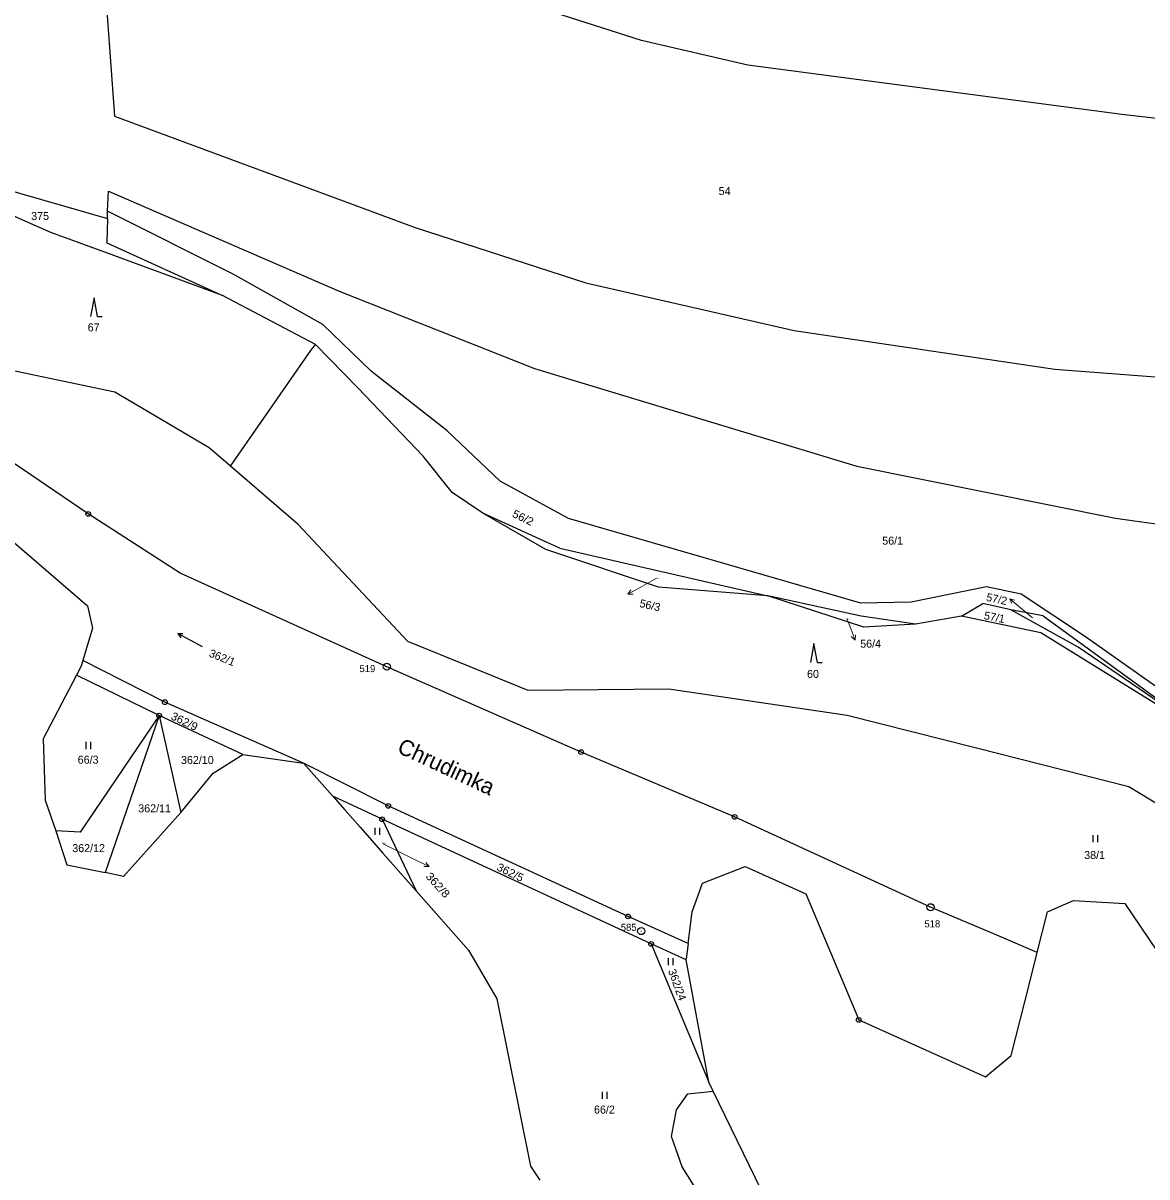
# Model space of a CAD drawing. Extents: x -645290 to -643454, y -1064771 to -1062356.
# Drawn here: x -645054.6 to -644815.8, y -1063831.9 to -1063586.8 of the extents above; entities that cross this region are included whole.
import ezdxf
from ezdxf.enums import TextEntityAlignment as Align

# ---------------------------------------------------------------- set-up
doc = ezdxf.new("R2010")
doc.units = 0
doc.header["$LTSCALE"] = 0.68
for name, color, linetype, lineweight in [('1', 7, 'Continuous', 25), ('3', 7, 'Continuous', 25), ('7', 7, 'Continuous', 13), ('8', 7, 'Continuous', 25)]:
    doc.layers.add(name, color=color, linetype=linetype, lineweight=lineweight)
doc.layers.add('2', color=7, linetype='Continuous')

msp = doc.modelspace()

# ---------------------------------------------------------------- linework, layer by layer
at = {"layer": '1'}
for p, q in [((-645037.39, -1063575.72), (-645035.2, -1063606.63)), ((-644923.22, -1063590.57), (-644955.84, -1063580.06)), ((-644900.64, -1063595.8), (-644923.22, -1063590.57)), ((-645035.2, -1063606.63), (-644971.28, -1063630.27)), ((-645077.13, -1063616.7), (-645036.68, -1063628.33)), ((-645036.68, -1063626.75), (-645036.45, -1063622.56)), ((-645036.45, -1063622.56), (-644987.44, -1063643.75)), ((-645048.68, -1063631.3), (-645056.54, -1063627.86)), ((-645036.68, -1063628.33), (-645036.8, -1063633.48)), ((-645009.97, -1063640.16), (-645036.68, -1063626.75)), ((-645036.68, -1063628.33), (-645036.68, -1063626.75)), ((-644971.28, -1063630.27), (-644935.04, -1063642.01)), ((-645036.67, -1063635.73), (-645048.68, -1063631.3)), ((-645036.8, -1063633.48), (-645012.26, -1063644.72)), ((-645012.26, -1063644.72), (-645036.67, -1063635.73)), ((-644990.92, -1063650.83), (-645009.97, -1063640.16)), ((-644935.04, -1063642.01), (-644890.77, -1063652.13)), ((-644992.5, -1063655.08), (-645012.26, -1063644.72)), ((-644987.44, -1063643.75), (-644945.91, -1063660.23)), ((-644980.61, -1063660.75), (-644990.92, -1063650.83)), ((-644890.77, -1063652.13), (-644835.38, -1063660.34)), ((-644993.43, -1063656.41), (-644992.5, -1063655.08)), ((-644983.44, -1063664.29), (-644992.5, -1063655.08)), ((-645035.11, -1063665.23), (-645077.33, -1063656.4)), ((-645010.56, -1063680.93), (-644993.43, -1063656.41)), ((-644945.91, -1063660.23), (-644877.43, -1063680.92)), ((-644835.38, -1063660.34), (-644689.27, -1063671.65)), ((-644964.52, -1063673.44), (-644980.61, -1063660.75)), ((-645040.74, -1063691.07), (-645081, -1063663.79)), ((-645015.07, -1063677.06), (-645035.11, -1063665.23)), ((-644969.61, -1063678.8), (-644983.44, -1063664.29)), ((-644953.26, -1063684.13), (-644964.52, -1063673.44)), ((-645010.56, -1063680.93), (-645015.07, -1063677.06)), ((-644963.43, -1063686.56), (-644969.61, -1063678.8)), ((-644996.13, -1063693.34), (-645010.56, -1063680.93)), ((-644877.43, -1063680.92), (-644822.46, -1063691.96)), ((-644938.68, -1063692.04), (-644953.26, -1063684.13)), ((-644956.94, -1063690.9), (-644963.43, -1063686.56)), ((-645021.2, -1063703.67), (-645040.74, -1063691.07)), ((-644943.5, -1063698.61), (-644956.94, -1063690.9)), ((-644942.48, -1063697.49), (-644956.94, -1063690.9)), ((-644876.6, -1063710.02), (-644938.68, -1063692.04)), ((-644822.46, -1063691.96), (-644735.89, -1063704.48)), ((-644972.84, -1063718.15), (-644996.13, -1063693.34)), ((-645056.41, -1063697.24), (-645040.92, -1063710.61)), ((-644919.61, -1063706.64), (-644943.5, -1063698.61)), ((-644940.52, -1063698.38), (-644942.48, -1063697.49)), ((-644940.52, -1063698.38), (-644896.38, -1063708.49)), ((-644977.31, -1063723.54), (-645021.2, -1063703.67)), ((-644896.38, -1063708.49), (-644919.61, -1063706.64)), ((-644849.92, -1063706.6), (-644865.92, -1063709.86)), ((-644842.55, -1063708.11), (-644849.92, -1063706.6)), ((-644875.96, -1063715.13), (-644896.38, -1063708.49)), ((-644876.56, -1063712.82), (-644896.38, -1063708.49)), ((-644828.89, -1063717.17), (-644842.55, -1063708.11)), ((-645040.92, -1063710.61), (-645039.83, -1063715.33)), ((-644865.92, -1063709.86), (-644876.6, -1063710.02)), ((-644855.18, -1063712.82), (-644850.64, -1063710.13)), ((-644847.85, -1063710.75), (-644850.64, -1063710.13)), ((-644844.76, -1063711.44), (-644847.85, -1063710.75)), ((-644837.89, -1063712.72), (-644844.76, -1063711.44)), ((-644830.45, -1063719.37), (-644844.76, -1063711.44)), ((-644864.98, -1063714.47), (-644876.56, -1063712.82)), ((-644864.98, -1063714.47), (-644875.96, -1063715.13)), ((-644855.18, -1063712.82), (-644864.98, -1063714.47)), ((-644838.33, -1063716.31), (-644855.18, -1063712.82)), ((-644837.89, -1063712.72), (-644802.37, -1063738.6)), ((-645039.83, -1063715.33), (-645041.91, -1063722.25)), ((-644802.37, -1063738.6), (-644838.33, -1063716.31)), ((-644959.58, -1063723.58), (-644972.84, -1063718.15)), ((-644802.37, -1063738.6), (-644830.45, -1063719.37)), ((-644801.78, -1063736.38), (-644828.89, -1063717.17)), ((-645042.27, -1063723.44), (-645043.26, -1063725.33)), ((-645041.91, -1063722.25), (-645042.27, -1063723.44)), ((-645024.48, -1063731.07), (-645041.91, -1063722.25)), ((-644936.02, -1063741.68), (-644977.31, -1063723.54)), ((-644947.26, -1063728.61), (-644959.58, -1063723.58)), ((-645043.26, -1063725.33), (-645050.3, -1063738.87)), ((-645025.69, -1063733.91), (-645043.26, -1063725.33)), ((-644917.4, -1063728.32), (-644947.26, -1063728.61)), ((-644879.52, -1063733.87), (-644917.4, -1063728.32)), ((-644995.02, -1063744.01), (-645024.48, -1063731.07)), ((-645025.69, -1063733.91), (-645042.47, -1063758.7)), ((-645025.69, -1063733.91), (-645037.16, -1063767.28)), ((-645025.69, -1063733.91), (-645021.09, -1063754.5)), ((-645007.88, -1063742.2), (-645025.69, -1063733.91)), ((-644852.01, -1063740.86), (-644879.52, -1063733.87)), ((-645050.3, -1063738.87), (-645049.88, -1063751.85)), ((-644819.68, -1063749.08), (-644852.01, -1063740.86)), ((-645014.21, -1063746.17), (-645007.88, -1063742.2)), ((-645007.88, -1063742.2), (-644995.02, -1063744.01)), ((-644903.41, -1063755.44), (-644936.02, -1063741.68)), ((-645021.09, -1063754.5), (-645014.21, -1063746.17)), ((-644995.02, -1063744.01), (-644988.81, -1063751.06)), ((-644977, -1063753.1), (-644995.02, -1063744.01)), ((-644988.81, -1063751.06), (-644986.24, -1063753.97)), ((-644978.33, -1063755.93), (-644988.81, -1063751.06)), ((-644797.01, -1063762.84), (-644819.68, -1063749.08)), ((-645049.88, -1063751.85), (-645047.62, -1063758.37)), ((-644926.06, -1063776.59), (-644977, -1063753.1)), ((-645033.25, -1063768.07), (-645021.09, -1063754.5)), ((-644986.24, -1063753.97), (-644983.01, -1063757.63)), ((-644978.33, -1063755.93), (-644971.11, -1063771.12)), ((-644921.15, -1063782.41), (-644978.33, -1063755.93)), ((-644861.79, -1063774.62), (-644903.41, -1063755.44)), ((-645047.62, -1063758.37), (-645045.3, -1063765.62)), ((-645042.47, -1063758.7), (-645047.62, -1063758.37)), ((-644983.01, -1063757.63), (-644978.14, -1063763.15)), ((-644978.14, -1063763.15), (-644971.11, -1063771.12)), ((-645045.3, -1063765.62), (-645037.16, -1063767.28)), ((-644910.27, -1063769.49), (-644901.16, -1063765.96)), ((-644901.16, -1063765.96), (-644888.29, -1063771.77)), ((-645033.25, -1063768.07), (-645037.16, -1063767.28)), ((-644959.99, -1063783.73), (-644971.11, -1063771.12)), ((-644888.29, -1063771.77), (-644880.73, -1063789.75)), ((-644836.94, -1063775.57), (-644831.41, -1063773.21)), ((-644831.41, -1063773.21), (-644820.53, -1063773.82)), ((-644847.69, -1063780.58), (-644861.79, -1063774.62)), ((-644839.12, -1063784.26), (-644836.94, -1063775.57)), ((-644820.53, -1063773.82), (-644806.4, -1063794.75)), ((-644913.31, -1063782.3), (-644926.06, -1063776.59)), ((-644839.12, -1063784.26), (-644847.69, -1063780.58)), ((-644921.15, -1063782.41), (-644908.86, -1063811.78)), ((-644913.7, -1063785.77), (-644921.15, -1063782.41)), ((-644913.31, -1063782.3), (-644913.74, -1063785.6)), ((-644959.99, -1063783.73), (-644953.94, -1063794.06)), ((-644840.77, -1063790.82), (-644839.12, -1063784.26)), ((-644913.7, -1063785.77), (-644913.74, -1063785.6)), ((-644910.35, -1063803.81), (-644913.7, -1063785.77)), ((-644880.73, -1063789.75), (-644877.03, -1063798.56)), ((-644844.62, -1063806.15), (-644840.77, -1063790.82)), ((-644953.94, -1063794.06), (-644949.02, -1063818.39)), ((-644877.03, -1063798.56), (-644850.13, -1063810.68)), ((-644908.86, -1063811.78), (-644910.35, -1063803.81)), ((-644850.13, -1063810.68), (-644844.62, -1063806.15)), ((-644907.94, -1063813.66), (-644908.86, -1063811.78)), ((-644915.79, -1063817.67), (-644913.35, -1063814.26)), ((-644913.35, -1063814.26), (-644907.94, -1063813.66)), ((-644895.47, -1063839.34), (-644907.94, -1063813.66)), ((-644949.02, -1063818.39), (-644946.76, -1063829.65)), ((-644916.86, -1063823.3), (-644915.79, -1063817.67)), ((-644914.53, -1063829.77), (-644916.86, -1063823.3)), ((-644946.76, -1063829.65), (-644944.81, -1063832.58)), ((-644906.32, -1063842.75), (-644914.53, -1063829.77))]:
    msp.add_line(p, q, dxfattribs=at)
for points in [[(-644756.87, -1063613.51), (-644820.57, -1063606.3), (-644900.64, -1063595.8)], [(-644913.31, -1063782.3), (-644912.45, -1063775.61), (-644910.27, -1063769.49)]]:
    msp.add_lwpolyline(points, dxfattribs=at)
at = {"layer": '3'}
for p, q in [((-645038.76, -1063649.19), (-645037.764, -1063649.19)), ((-645021.74, -1063716.476), (-645020.642, -1063716.492)), ((-644885.81, -1063722.64), (-644884.814, -1063722.64)), ((-645041.191, -1063741.02), (-645041.191, -1063739.52)), ((-645040.19, -1063741.02), (-645040.19, -1063739.52)), ((-644979.811, -1063759.26), (-644979.811, -1063757.76)), ((-644978.81, -1063759.26), (-644978.81, -1063757.76)), ((-644827.261, -1063760.84), (-644827.261, -1063759.34)), ((-644826.26, -1063760.84), (-644826.26, -1063759.34)), ((-644917.481, -1063786.91), (-644917.481, -1063785.41)), ((-644916.48, -1063786.91), (-644916.48, -1063785.41)), ((-644931.491, -1063815.33), (-644931.491, -1063813.83)), ((-644930.49, -1063815.33), (-644930.49, -1063813.83))]:
    msp.add_line(p, q, dxfattribs=at)
for points in [[(-645038.76, -1063649.19), (-645039.51, -1063645.19), (-645040.26, -1063649.19)], [(-645016.442, -1063719.293), (-645021.74, -1063716.476), (-645021.113, -1063717.377)], [(-644885.81, -1063722.64), (-644886.56, -1063718.64), (-644887.31, -1063722.64)]]:
    msp.add_lwpolyline(points, dxfattribs=at)
at = {"layer": '7'}
for p, q in [((-644926.085, -1063708.155), (-644924.966, -1063708.107)), ((-644844.969, -1063709.111), (-644844.524, -1063710.138)), ((-644877.805, -1063717.872), (-644877.696, -1063716.757)), ((-644968.323, -1063765.996), (-644969.003, -1063765.106))]:
    msp.add_line(p, q, dxfattribs=at)
for points in [[(-644919.99, -1063704.76), (-644923.46, -1063706.7), (-644926.085, -1063708.155), (-644925.452, -1063707.231)], [(-644840.11, -1063713.17), (-644842.67, -1063711.04), (-644844.969, -1063709.111), (-644843.88, -1063709.371)], [(-644879.55, -1063713.29), (-644878.88, -1063715.07), (-644877.805, -1063717.872), (-644878.631, -1063717.116)], [(-644978.24, -1063761.09), (-644971.02, -1063764.68), (-644968.323, -1063765.996), (-644969.442, -1063766.007)]]:
    msp.add_lwpolyline(points, dxfattribs=at)
at = {"layer": '8'}
for centre, radius in [((-645040.74, -1063691.0699), 0.5), ((-645040.74, -1063691.0699), 0.0303), ((-644977.31, -1063723.5398), 0.75), ((-644977.31, -1063723.5398), 0.03), ((-645024.48, -1063731.0699), 0.5), ((-645024.48, -1063731.0699), 0.0303), ((-645025.69, -1063733.9099), 0.5), ((-645025.69, -1063733.9099), 0.0303), ((-644936.02, -1063741.6799), 0.5), ((-644936.02, -1063741.6799), 0.0303), ((-644977, -1063753.0999), 0.5), ((-644977, -1063753.0999), 0.0303), ((-644978.33, -1063755.9299), 0.5), ((-644978.33, -1063755.9299), 0.0303), ((-644903.41, -1063755.4399), 0.5), ((-644903.41, -1063755.4399), 0.0303), ((-644861.79, -1063774.6198), 0.75), ((-644861.79, -1063774.6198), 0.03), ((-644926.06, -1063776.5899), 0.5), ((-644926.06, -1063776.5899), 0.0303), ((-644923.27, -1063779.6998), 0.75), ((-644923.27, -1063779.6998), 0.03), ((-644921.15, -1063782.4099), 0.5), ((-644921.15, -1063782.4099), 0.0303), ((-644877.03, -1063798.5599), 0.5), ((-644877.03, -1063798.5599), 0.0303)]:
    msp.add_circle(centre, radius, dxfattribs=at)

# ---------------------------------------------------------------- texts
at = {"layer": '2'}
for s, height, p in [('54', 1.7, (-644906.81, -1063623.354)), ('375', 1.7, (-645052.88, -1063628.655)), ('56/1', 1.7, (-644872.05, -1063697.615)), ('56/3', 0.2, (-644919.99, -1063704.81)), ('57/2', 0.2, (-644840.11, -1063713.219)), ('362/10', 1.7, (-645021.05, -1063744.205)), ('362/11', 1.7, (-645030.13, -1063754.475)), ('362/8', 0.2, (-644978.24, -1063761.14))]:
    msp.add_text(s, height=height, dxfattribs=at).set_placement(p)
for s, p in [('67', (-645039.609, -1063652.314)), ('60', (-644886.769, -1063725.925)), ('66/3', (-645040.779, -1063744.145)), ('362/12', (-645040.67, -1063762.925)), ('38/1', (-644826.929, -1063764.385)), ('66/2', (-644931.079, -1063818.455))]:
    msp.add_text(s, height=1.7, dxfattribs=at).set_placement(p, align=Align.CENTER)
for s, rotation, width, p in [('56/2', 334, 1.05, (-644950.826, -1063691.631)), ('362/8', 312, 1.1, (-644969.186, -1063768.156))]:
    msp.add_text(s, height=1.7, rotation=rotation, dxfattribs=dict(at, width=width)).set_placement(p)
for s, rotation, p in [('56/3', 347, (-644919.4304, -1063711.8184)), ('57/2', 348, (-644845.7374, -1063710.4536))]:
    msp.add_text(s, height=1.7, rotation=rotation, dxfattribs=at).set_placement(p, align=Align.RIGHT)
for s, height, rotation, p in [('57/1', 1.7, 349, (-644850.531, -1063713.437)), ('56/4', 0.2, 335, (-644879.571, -1063713.335)), ('362/24', 1.7, 290, (-644917.589, -1063788.115))]:
    msp.add_text(s, height=height, rotation=rotation, dxfattribs=at).set_placement(p)
msp.add_text('56/4', height=1.7, dxfattribs=at).set_placement((-644872.309, -1063719.495), align=Align.RIGHT)
msp.add_text('362/1', height=1.7, rotation=338, dxfattribs=at).set_placement((-645012.6064, -1063722.3889), align=Align.CENTER)
at = {"layer": '2', "width": 1.05}
for s, p in [('362/9', (-645020.6866, -1063735.9136)), ('362/5', (-644951.4466, -1063767.9936))]:
    msp.add_text(s, height=1.7, rotation=334, dxfattribs=at).set_placement(p, align=Align.CENTER)
at = {"layer": '7'}
msp.add_text('Chrudimka', height=3.4, rotation=335, dxfattribs=at).set_placement((-644975.339, -1063741.66))
at = {"layer": '8'}
for s, p in [('519', (-644979.769, -1063724.687)), ('585', (-644924.249, -1063779.637)), ('518', (-644859.729, -1063778.907))]:
    msp.add_text(s, height=1.5, dxfattribs=at).set_placement(p, align=Align.RIGHT)

doc.saveas('drawing.dxf')
